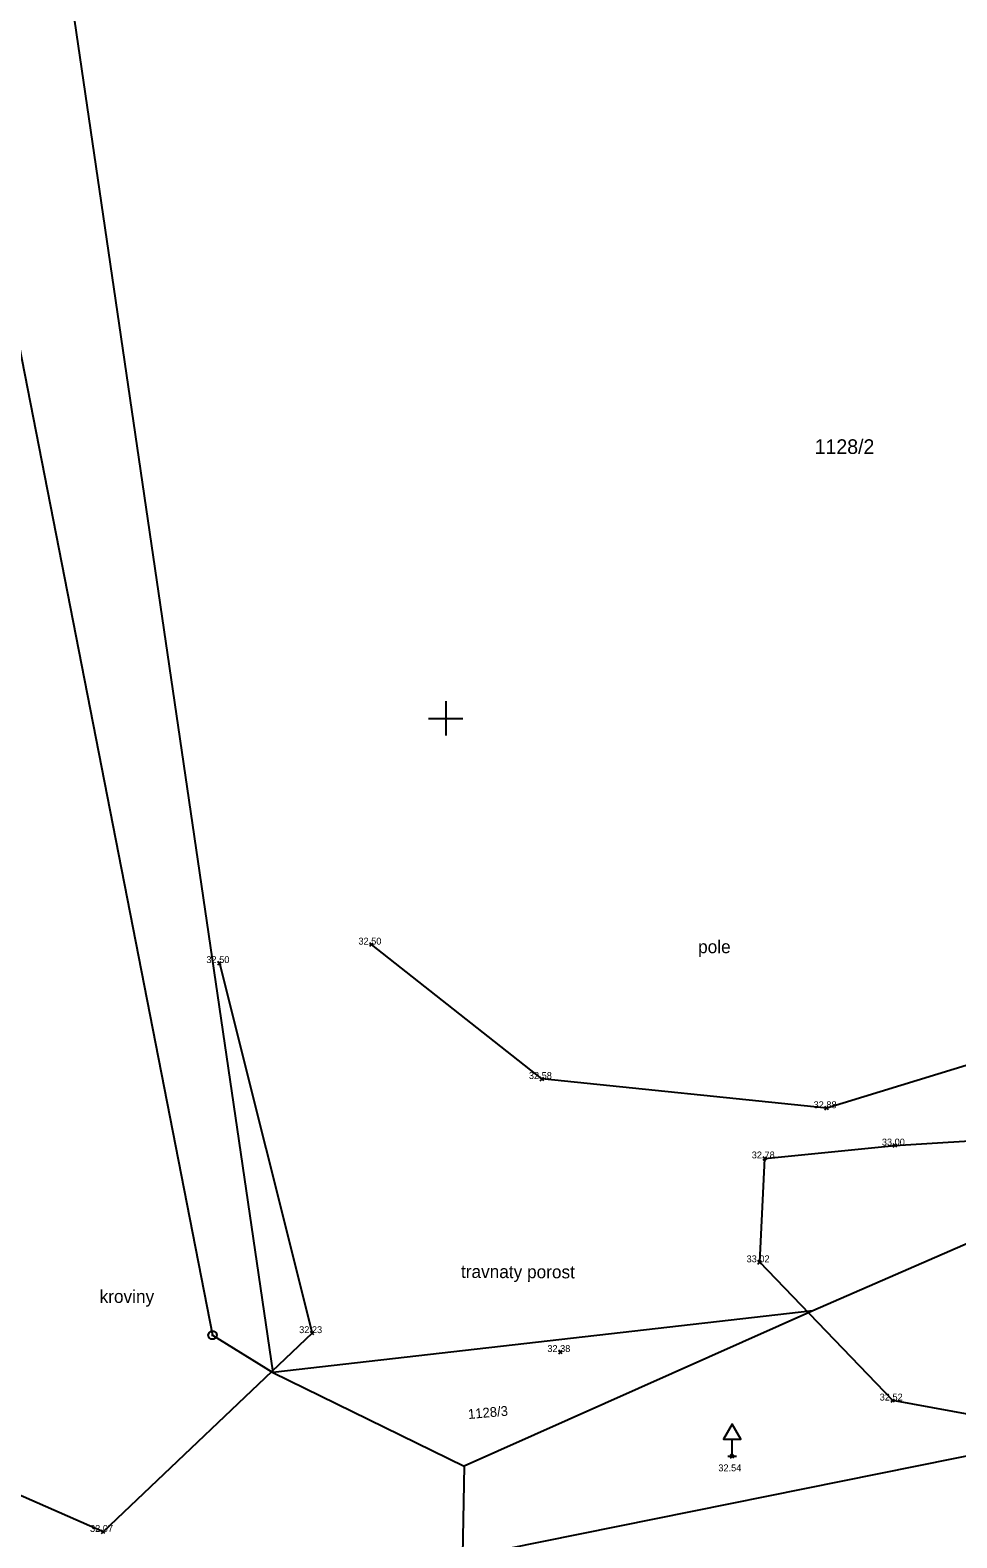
# Model space of a CAD drawing. Extents: x -772865 to -772533, y -1034366 to -1034132.
# Drawn here: x -772834.68 to -772813.1, y -1034294.09 to -1034258.97 of the extents above; entities that cross this region are included whole.
import ezdxf

# ---------------------------------------------------------------- set-up
doc = ezdxf.new("R2010")
doc.units = 0
for name, color, linetype in [('body', 7, 'Continuous'), ('dopravni_znacky', 7, 'Continuous'), ('KM_hranice', 7, 'Continuous'), ('KM_mezni_znaky', 7, 'Continuous'), ('KM_parcelni_cisla', 7, 'Continuous'), ('mistni_popis', 7, 'Continuous'), ('oddeleni_ploch', 7, 'Continuous'), ('souradnicova_sit', 7, 'Continuous'), ('stromy_kere', 7, 'Continuous'), ('vyskove_koty', 7, 'Continuous')]:
    doc.layers.add(name, color=color, linetype=linetype)

msp = doc.modelspace()

# ---------------------------------------------------------------- linework, layer by layer
at = {"layer": 'body'}
for p, q in [((-772826.69, -1034280.31), (-772826.77, -1034280.23)), ((-772826.77, -1034280.31), (-772826.69, -1034280.23)), ((-772830.23, -1034280.74), (-772830.31, -1034280.66)), ((-772830.31, -1034280.74), (-772830.23, -1034280.66)), ((-772822.72, -1034283.44), (-772822.8, -1034283.36)), ((-772822.8, -1034283.44), (-772822.72, -1034283.36)), ((-772816.09, -1034284.12), (-772816.17, -1034284.04)), ((-772816.17, -1034284.12), (-772816.09, -1034284.04)), ((-772814.5, -1034284.99), (-772814.58, -1034284.91)), ((-772814.58, -1034284.99), (-772814.5, -1034284.91)), ((-772817.53, -1034285.29), (-772817.61, -1034285.21)), ((-772817.61, -1034285.29), (-772817.53, -1034285.21)), ((-772817.65, -1034287.71), (-772817.73, -1034287.63)), ((-772817.73, -1034287.71), (-772817.65, -1034287.63)), ((-772828.07, -1034289.36), (-772828.15, -1034289.28)), ((-772828.15, -1034289.36), (-772828.07, -1034289.28)), ((-772822.29, -1034289.8), (-772822.37, -1034289.72)), ((-772822.37, -1034289.8), (-772822.29, -1034289.72)), ((-772814.55, -1034290.93), (-772814.63, -1034290.85)), ((-772814.63, -1034290.93), (-772814.55, -1034290.85)), ((-772818.29, -1034292.23), (-772818.37, -1034292.15)), ((-772818.37, -1034292.23), (-772818.29, -1034292.15)), ((-772832.94, -1034293.99), (-772833.02, -1034293.91)), ((-772833.02, -1034293.99), (-772832.94, -1034293.91))]:
    msp.add_line(p, q, dxfattribs=at)
at = {"layer": 'dopravni_znacky'}
msp.add_line((-772818.43, -1034292.19), (-772818.23, -1034292.19), dxfattribs=at)
msp.add_lwpolyline([(-772818.33, -1034292.19), (-772818.33, -1034291.79), (-772818.13, -1034291.79), (-772818.33, -1034291.44), (-772818.53, -1034291.79), (-772818.33, -1034291.79)], dxfattribs=at)
at = {"layer": 'KM_hranice'}
for p, q in [((-772839.01, -1034245.51), (-772830.43, -1034289.37)), ((-772834.43, -1034253.39), (-772829.03, -1034290.24)), ((-772798.72, -1034281.08), (-772816.45, -1034288.8)), ((-772816.45, -1034288.8), (-772829.03, -1034290.24)), ((-772816.45, -1034288.8), (-772824.57, -1034292.42)), ((-772830.43, -1034289.37), (-772829.03, -1034290.24)), ((-772829.03, -1034290.24), (-772824.57, -1034292.42)), ((-772824.57, -1034292.42), (-772824.61, -1034294.49))]:
    msp.add_line(p, q, dxfattribs=at)
at = {"layer": 'KM_mezni_znaky'}
msp.add_line((-772830.454, -1034289.37), (-772830.406, -1034289.37), dxfattribs=at)
msp.add_lwpolyline([(-772830.4, -1034289.274), (-772830.35, -1034289.31), (-772830.33, -1034289.368), (-772830.35, -1034289.426), (-772830.4, -1034289.462), (-772830.462, -1034289.462), (-772830.512, -1034289.426), (-772830.532, -1034289.368), (-772830.512, -1034289.31), (-772830.462, -1034289.274)], close=True, dxfattribs=at)
at = {"layer": 'oddeleni_ploch'}
for points in [[(-772574.1, -1034196.14), (-772586.87, -1034201.34), (-772598.23, -1034205.06), (-772614.53, -1034207.42), (-772626.93, -1034206.95), (-772636.66, -1034207.26), (-772647.96, -1034208.36), (-772659.39, -1034213.08), (-772672.58, -1034218.62), (-772687.49, -1034225.14), (-772703.01, -1034232.02), (-772714.35, -1034236.9), (-772728.88, -1034243.07), (-772737.97, -1034245.74), (-772746.8, -1034246.99), (-772753.85, -1034250.11), (-772762.71, -1034257.3), (-772782.05, -1034269.18), (-772797.09, -1034276.39), (-772810.61, -1034282.39), (-772816.13, -1034284.08), (-772822.76, -1034283.4), (-772826.73, -1034280.27)], [(-772569.67, -1034207.72), (-772578.35, -1034211.18), (-772588.33, -1034216.15), (-772592.11, -1034217.46), (-772598.89, -1034219.1), (-772610.21, -1034219.57), (-772621.14, -1034219.48), (-772637.34, -1034221.06), (-772647.54, -1034222.08), (-772674.34, -1034233.24), (-772685.01, -1034239.21), (-772697.33, -1034242.95), (-772712.12, -1034249.56), (-772725.85, -1034254.8), (-772738.85, -1034261.98), (-772750.37, -1034267.76), (-772764, -1034272.65), (-772783.9, -1034280.59), (-772796.38, -1034286.28), (-772810.31, -1034291.67), (-772823.61, -1034294.35), (-772828.52, -1034296.12), (-772827.01, -1034302.81), (-772823.23, -1034300.75)]]:
    msp.add_lwpolyline(points, dxfattribs=at)
at = {"layer": 'souradnicova_sit'}
for p, q in [((-772825, -1034274.6), (-772825, -1034275.4)), ((-772825.4, -1034275), (-772824.6, -1034275))]:
    msp.add_line(p, q, dxfattribs=at)
at = {"layer": 'stromy_kere'}
for points in [[(-772790.87, -1034282.58), (-772810.31, -1034291.67), (-772814.59, -1034290.89), (-772817.69, -1034287.67), (-772817.57, -1034285.25), (-772814.54, -1034284.95), (-772809.31, -1034284.62), (-772804.85, -1034281.87), (-772792.97, -1034276.8), (-772780.79, -1034270.56)], [(-772830.27, -1034280.7), (-772828.11, -1034289.32), (-772832.98, -1034293.95), (-772835.15, -1034292.99), (-772836.45, -1034289.83)]]:
    msp.add_lwpolyline(points, dxfattribs=at)

# ---------------------------------------------------------------- texts
at = {"layer": 'KM_parcelni_cisla'}
msp.add_text('1128/2', height=0.34, dxfattribs=at).set_placement((-772816.41, -1034268.84))
msp.add_text('1128/3', height=0.228, rotation=4.9847, dxfattribs=at).set_placement((-772824.473, -1034291.322))
at = {"layer": 'mistni_popis'}
for s, p in [('pole', (-772819.124, -1034280.47)), ('kroviny', (-772833.062, -1034288.616))]:
    msp.add_text(s, height=0.3, dxfattribs=at).set_placement(p)
msp.add_text('travnaty porost', height=0.3, rotation=359.7602, dxfattribs=at).set_placement((-772824.647, -1034288.034))
at = {"layer": 'vyskove_koty'}
for s, p in [('32.50', (-772827.035, -1034280.27)), ('32.50', (-772830.575, -1034280.7)), ('32.58', (-772823.065, -1034283.4)), ('32.88', (-772816.435, -1034284.08)), ('33.00', (-772814.845, -1034284.95)), ('32.78', (-772817.875, -1034285.25)), ('33.02', (-772817.995, -1034287.67)), ('32.23', (-772828.415, -1034289.32)), ('32.38', (-772822.635, -1034289.76)), ('32.52', (-772814.895, -1034290.89)), ('32.54', (-772818.653, -1034292.539)), ('32.07', (-772833.285, -1034293.95))]:
    msp.add_text(s, height=0.16, dxfattribs=at).set_placement(p)

doc.saveas('drawing.dxf')
